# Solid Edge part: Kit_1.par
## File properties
Sűrűség: 0,000 kg/m^3
Pontosság: 0,990
Author: bmolnar
Last saved by: bmolnar
Revision: 77
Username: bmolnar
Dokumentum tartalom típus: 0
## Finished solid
Body 1: solid body, 46 faces, 63 edges, 53 vertices.
  Faces by surface: cylinder 15, cone 14, plane 12, torus 5
  Edges by curve: circle 49, line 14
Bounding box of the edges (mm; curved faces can reach further): 106.000 x 105.975 x 21.350, from (-53, -50.85, 95.1) to (53, 55.125, 116.45).
Cylindrical faces by radius (mm): R1.75 x2, R3.5 x4, R12.8 x1, R13.45 x1, R14 x1, R14.9 x1, R15 x1, R28 x1, R46.625 x1, R50.85 x1, R53 x1
Conical faces (half-angle, radius in mm at the cone's reference point): 3 deg R14.95 x1, 7 deg R14.2695 x1, 14 deg R12.65 x1, 14 deg R13.057 x1, 17 deg R12.65 x1, 23 deg R13.4211 x1, 42.5 deg R12.637 x1, 45 deg R13.7 x1, 45 deg R14.1 x1, 45 deg R27.25 x1, 60 deg R34.6072 x1, 84 deg R13.012 x1, 85 deg R14.6625 x1, 87 deg R12.7157 x1
Toroidal faces (ring radius, tube radius in mm): R13.4008 r0.225 x1, R13.8914 r0.325 x1, R14.7 r0.2 x1, R28.8 r0.8 x1, R41.2144 r0.8 x1
Planar faces by outward normal: +z 7, -z 3, oblique 2
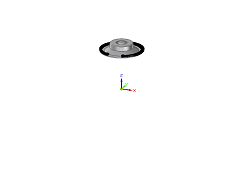
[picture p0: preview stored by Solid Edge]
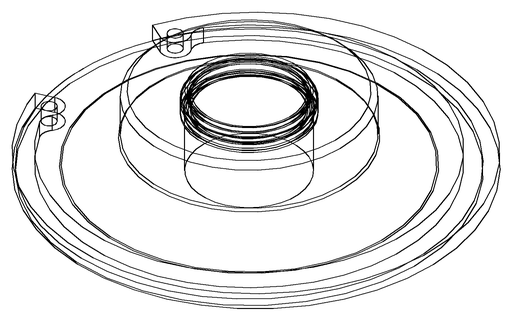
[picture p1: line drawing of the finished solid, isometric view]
